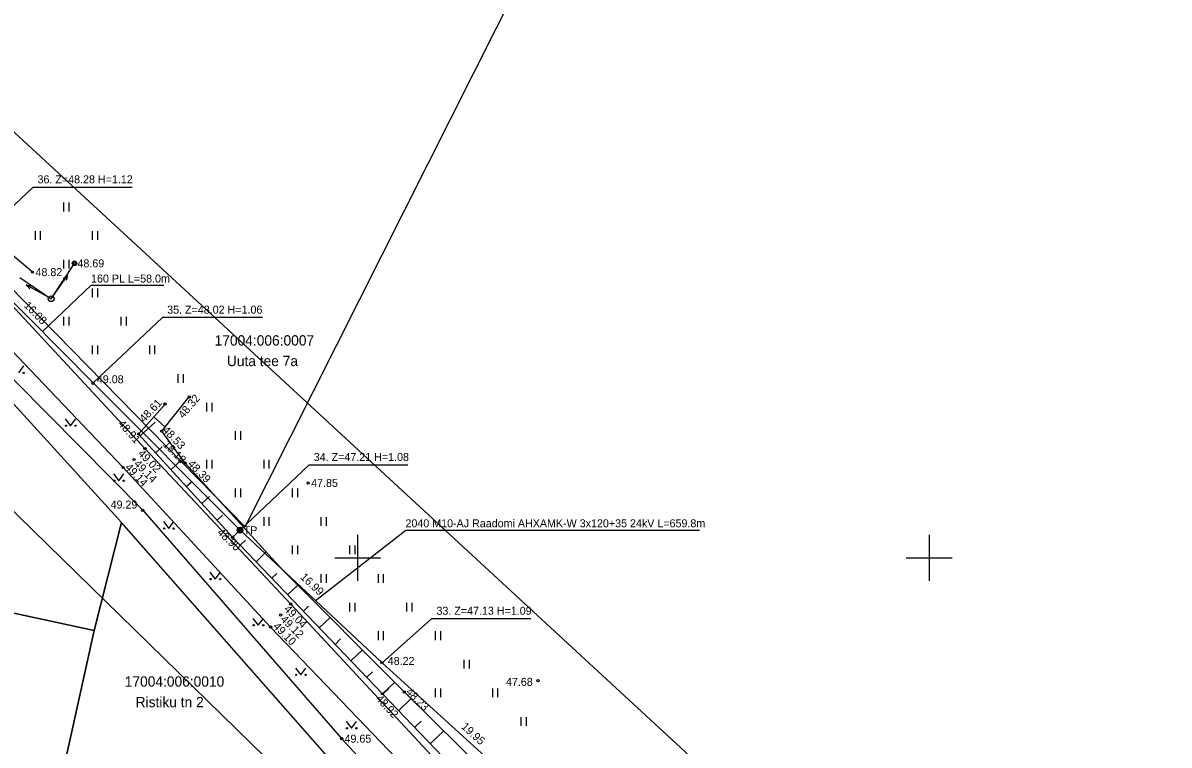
# Model space of a CAD drawing. Extents: x 642747 to 644424, y 6457048 to 6458238.
# Drawn here: x 643970.7 to 644071, y 6457583.6 to 6457646.8 of the extents above; entities that cross this region are included whole.
import ezdxf

# ---------------------------------------------------------------- set-up
doc = ezdxf.new("R2010")
doc.units = 0
for name, color, linetype in [('ABIJOONIS', 7, 'Continuous'), ('AED', 7, 'Continuous'), ('HALJASTUS', 7, 'Continuous'), ('JOONSIDE', 7, 'Continuous'), ('KOORDPUNKT', 7, 'Continuous'), ('KORGUS', 7, 'Continuous'), ('KPKAABEL', 7, 'Continuous'), ('MOOTPIIR', 7, 'Continuous'), ('MPOHULIIN', 7, 'Continuous'), ('PIIR', 7, 'Continuous'), ('POST', 7, 'Continuous'), ('RELJEEF', 7, 'Continuous'), ('TEE', 7, 'Continuous'), ('VORK', 7, 'Continuous')]:
    doc.layers.add(name, color=color, linetype=linetype)

msp = doc.modelspace()

# ---------------------------------------------------------------- linework, layer by layer
at = {"layer": 'ABIJOONIS'}
for points in [[(643972.43, 6457619.79), (643976.71, 6457623.84), (643983.07, 6457623.84)], [(643996.31, 6457596.27), (644004.21, 6457602.42), (644029.91, 6457602.42)]]:
    msp.add_lwpolyline(points, dxfattribs=at)
at = {"layer": 'AED'}
msp.add_line((643971.57, 6457624.99), (643955.99, 6457638.18), dxfattribs=at)
at = {"layer": 'HALJASTUS'}
for p, q in [((643974.29, 6457631.07), (643974.29, 6457630.31)), ((643974.75, 6457631.07), (643974.75, 6457630.31)), ((643971.79, 6457628.57), (643971.79, 6457627.81)), ((643972.25, 6457628.57), (643972.25, 6457627.81)), ((643976.79, 6457628.57), (643976.79, 6457627.81)), ((643977.25, 6457628.57), (643977.25, 6457627.81)), ((643974.29, 6457626.07), (643974.29, 6457625.31)), ((643974.75, 6457626.07), (643974.75, 6457625.31)), ((643976.79, 6457623.57), (643976.79, 6457622.81)), ((643977.25, 6457623.57), (643977.25, 6457622.81)), ((643974.29, 6457621.07), (643974.29, 6457620.31)), ((643974.75, 6457621.07), (643974.75, 6457620.31)), ((643979.29, 6457621.07), (643979.29, 6457620.31)), ((643979.75, 6457621.07), (643979.75, 6457620.31)), ((643976.79, 6457618.57), (643976.79, 6457617.81)), ((643977.25, 6457618.57), (643977.25, 6457617.81)), ((643981.79, 6457618.57), (643981.79, 6457617.81)), ((643982.25, 6457618.57), (643982.25, 6457617.81)), ((643970.37, 6457616.18), (643970.82, 6457616.79)), ((643984.29, 6457616.07), (643984.29, 6457615.31)), ((643984.75, 6457616.07), (643984.75, 6457615.31)), ((643986.79, 6457613.57), (643986.79, 6457612.81)), ((643987.25, 6457613.57), (643987.25, 6457612.81)), ((643974.44, 6457612.17), (643974.9, 6457611.56)), ((643974.9, 6457611.56), (643975.35, 6457612.17)), ((643989.29, 6457611.07), (643989.29, 6457610.31)), ((643989.75, 6457611.07), (643989.75, 6457610.31)), ((643986.79, 6457608.57), (643986.79, 6457607.81)), ((643987.25, 6457608.57), (643987.25, 6457607.81)), ((643991.79, 6457608.57), (643991.79, 6457607.81)), ((643992.25, 6457608.57), (643992.25, 6457607.81)), ((643978.66, 6457607.34), (643979.12, 6457606.74)), ((643979.12, 6457606.74), (643979.57, 6457607.34)), ((643989.29, 6457606.07), (643989.29, 6457605.31)), ((643989.75, 6457606.07), (643989.75, 6457605.31)), ((643994.29, 6457606.07), (643994.29, 6457605.31)), ((643994.75, 6457606.07), (643994.75, 6457605.31)), ((643983.02, 6457603.17), (643983.49, 6457602.56)), ((643983.49, 6457602.56), (643983.93, 6457603.17)), ((643991.79, 6457603.57), (643991.79, 6457602.81)), ((643992.25, 6457603.57), (643992.25, 6457602.81)), ((643996.79, 6457603.57), (643996.79, 6457602.81)), ((643997.25, 6457603.57), (643997.25, 6457602.81)), ((643994.29, 6457601.07), (643994.29, 6457600.31)), ((643994.75, 6457601.07), (643994.75, 6457600.31)), ((643999.29, 6457601.07), (643999.29, 6457600.31)), ((643999.75, 6457601.07), (643999.75, 6457600.31)), ((643987.09, 6457598.74), (643987.55, 6457598.14)), ((643987.55, 6457598.14), (643988, 6457598.74)), ((643996.79, 6457598.57), (643996.79, 6457597.81)), ((643997.25, 6457598.57), (643997.25, 6457597.81)), ((644001.79, 6457598.57), (644001.79, 6457597.81)), ((644002.25, 6457598.57), (644002.25, 6457597.81)), ((643999.29, 6457596.07), (643999.29, 6457595.31)), ((643999.75, 6457596.07), (643999.75, 6457595.31)), ((644004.29, 6457596.07), (644004.29, 6457595.31)), ((644004.75, 6457596.07), (644004.75, 6457595.31)), ((643990.85, 6457594.7), (643991.32, 6457594.1)), ((643991.32, 6457594.1), (643991.76, 6457594.7)), ((644001.79, 6457593.57), (644001.79, 6457592.81)), ((644002.25, 6457593.57), (644002.25, 6457592.81)), ((644006.79, 6457593.57), (644006.79, 6457592.81)), ((644007.25, 6457593.57), (644007.25, 6457592.81)), ((644009.29, 6457591.07), (644009.29, 6457590.31)), ((644009.75, 6457591.07), (644009.75, 6457590.31)), ((643994.57, 6457590.36), (643995.03, 6457589.76)), ((643995.03, 6457589.76), (643995.47, 6457590.36)), ((644006.79, 6457588.57), (644006.79, 6457587.81)), ((644007.25, 6457588.57), (644007.25, 6457587.81)), ((644011.79, 6457588.57), (644011.79, 6457587.81)), ((644012.25, 6457588.57), (644012.25, 6457587.81)), ((644014.29, 6457586.07), (644014.29, 6457585.31)), ((644014.75, 6457586.07), (644014.75, 6457585.31)), ((643999.01, 6457585.69), (643999.48, 6457585.09)), ((643999.48, 6457585.09), (643999.92, 6457585.69))]:
    msp.add_line(p, q, dxfattribs=at)
msp.add_lwpolyline([(643947.9, 6457637.83), (643981.21, 6457604.16), (643998.6, 6457584.18), (644020.54, 6457560.41), (644029.92, 6457549.51)], dxfattribs=at)
for centre in [(643970.8, 6457616.18), (643974.5, 6457611.56), (643975.33, 6457611.56), (643978.72, 6457606.74), (643979.55, 6457606.74), (643983.09, 6457602.56), (643983.91, 6457602.56), (643987.15, 6457598.14), (643987.98, 6457598.14), (643990.92, 6457594.1), (643991.75, 6457594.1), (643994.63, 6457589.76), (643995.46, 6457589.76), (643999.08, 6457585.09), (643999.9, 6457585.09)]:
    msp.add_circle(centre, 0.055, dxfattribs=at)
at = {"layer": 'KOORDPUNKT'}
for p, q in [((643965.56, 6457626.7), (643971.59, 6457632.41)), ((643980.3, 6457632.41), (643971.59, 6457632.41)), ((643976.89, 6457615.31), (643982.93, 6457621.01)), ((643991.68, 6457621.01), (643982.93, 6457621.01)), ((643989.72, 6457602.42), (643995.75, 6457608.12)), ((644004.39, 6457608.12), (643995.75, 6457608.12)), ((644002.15, 6457590.82), (644006.48, 6457594.67)), ((644015.15, 6457594.67), (644006.48, 6457594.67))]:
    msp.add_line(p, q, dxfattribs=at)
for points in [[(643976.89, 6457615.31), (643976.89, 6457615.31), (643976.89, 6457615.31)], [(643989.72, 6457602.42), (643989.72, 6457602.42), (643989.72, 6457602.42)], [(644002.15, 6457590.82), (644002.15, 6457590.82), (644002.15, 6457590.82)]]:
    msp.add_lwpolyline(points, dxfattribs=at)
at = {"layer": 'KORGUS'}
for centre in [(643971.57, 6457624.99), (643975.24, 6457625.76), (643976.85, 6457615.27), (643985.28, 6457614.08), (643983.17, 6457613.45), (643980.84, 6457610.82), (643982.87, 6457611.08), (643981.4, 6457609.56), (643979.5, 6457607.9), (643980.45, 6457608.6), (643984.91, 6457608.29), (643995.68, 6457606.55), (643981.21, 6457604.16), (643989.07, 6457601.8), (643994.16, 6457595.95), (643993.27, 6457594.99), (643992.4, 6457593.94), (644002.15, 6457590.82), (644015.78, 6457589.26), (644002.18, 6457588.1), (644004.09, 6457588.27), (643998.6, 6457584.18)]:
    msp.add_circle(centre, 0.1, dxfattribs=at)
at = {"layer": 'KPKAABEL'}
for points in [[(644103.08, 6457652.71), (644111.13, 6457630.67), (644117.87, 6457612.3), (644117.83, 6457611.89), (644117.53, 6457611.59), (644112.75, 6457607.62), (644102.69, 6457600.12), (644092.7, 6457590.58), (644078.19, 6457577.56), (644066.52, 6457567.37), (644056.9, 6457559.14), (644048.86, 6457552.54), (644048.04, 6457551.93), (644047.16, 6457551.98), (644039.64, 6457557.84), (644029.55, 6457566.38), (644016.9, 6457577.4), (644002.15, 6457590.82), (643989.72, 6457602.42), (643976.89, 6457615.31), (643965.56, 6457626.7)], [(643989.72, 6457602.42), (643976.89, 6457615.31), (643965.56, 6457626.7), (643955.37, 6457636.99), (643948.85, 6457643.5)]]:
    msp.add_lwpolyline(points, dxfattribs=at)
at = {"layer": 'MOOTPIIR'}
msp.add_lwpolyline([(643525.45, 6457467.56), (643537.45, 6457435.46), (643944.85, 6457628.51), (644046.63, 6457529.09), (644067.02, 6457529.09), (644138.41, 6457598.4), (644075.1, 6457775.21), (644046.02, 6457752.58), (644092.47, 6457611.94), (644070.66, 6457576.37), (644041.98, 6457570.72), (643942.22, 6457662.86)], close=True, dxfattribs=at)
at = {"layer": 'MPOHULIIN'}
for p, q in [((643973.35, 6457622.86), (643974.63, 6457624.71)), ((643974.63, 6457624.71), (643974.25, 6457624.42)), ((643974.63, 6457624.71), (643974.5, 6457624.25)), ((643971.02, 6457623.87), (643971.34, 6457623.52)), ((643971.02, 6457623.87), (643971.48, 6457623.78)), ((643972.99, 6457622.78), (643971.02, 6457623.87))]:
    msp.add_line(p, q, dxfattribs=at)
at = {"layer": 'PIIR'}
for points in [[(643958.41, 6457676.3), (643948.83, 6457644.9), (643990.17, 6457602.7), (644016.12, 6457654.27)], [(643950.16, 6457635.14), (643942.8, 6457601.01), (643976.97, 6457593.64), (643979.35, 6457603.09)], [(643976.63, 6457515.36), (643982.89, 6457517.02), (644002.28, 6457577.05), (643979.35, 6457603.09), (643976.97, 6457593.64), (643971.26, 6457567.81), (643957.55, 6457524.74), (643955.72, 6457521.24)], [(643928.3, 6457534.06), (643957.55, 6457524.74), (643971.26, 6457567.81), (643976.97, 6457593.64), (643942.8, 6457601.01)]]:
    msp.add_lwpolyline(points, close=True, dxfattribs=at)
at = {"layer": 'POST'}
msp.add_lwpolyline([(643970.47, 6457624.51), (643973.2, 6457622.66), (643975.24, 6457625.76)], dxfattribs=at)
for centre, radius in [((643975.24, 6457625.76), 0.2), ((643973.2, 6457622.66), 0.25), ((643989.72, 6457602.42), 0.25), ((643989.72, 6457602.42), 0.225), ((643989.72, 6457602.42), 0.2), ((643989.72, 6457602.42), 0.175), ((643989.72, 6457602.42), 0.15), ((643989.72, 6457602.42), 0.125), ((643989.72, 6457602.42), 0.1), ((643989.72, 6457602.42), 0.075), ((643989.72, 6457602.42), 0.05), ((643989.72, 6457602.42), 0.025)]:
    msp.add_circle(centre, radius, dxfattribs=at)
at = {"layer": 'RELJEEF'}
for p, q in [((643982.17, 6457612.32), (643983.16, 6457611.44)), ((643980.98, 6457610.67), (643982.3, 6457611.87)), ((643982.33, 6457609.19), (643982.91, 6457609.72)), ((643983.68, 6457607.71), (643984.67, 6457608.62)), ((643985.02, 6457606.24), (643985.44, 6457606.61)), ((643986.37, 6457604.76), (643987.04, 6457605.37)), ((643987.72, 6457603.28), (643988.2, 6457603.72)), ((643989.07, 6457601.8), (643990.03, 6457602.68)), ((643989.73, 6457601.1), (643990.2, 6457601.55)), ((643991.12, 6457599.66), (643992.01, 6457600.52)), ((643992.5, 6457598.21), (643992.93, 6457598.63)), ((643993.88, 6457596.77), (643994.77, 6457597.62)), ((643995.26, 6457595.32), (643995.72, 6457595.76)), ((643996.65, 6457593.88), (643997.6, 6457594.79)), ((643998.03, 6457592.43), (643998.52, 6457592.9)), ((643999.41, 6457590.99), (644000.42, 6457591.95)), ((644000.79, 6457589.54), (644001.31, 6457590.04)), ((644002.18, 6457588.1), (644003.25, 6457589.12)), ((644002.21, 6457588.06), (644002.75, 6457588.57)), ((644003.59, 6457586.62), (644004.7, 6457587.68)), ((644004.98, 6457585.17), (644005.55, 6457585.72)), ((644006.36, 6457583.73), (644007.54, 6457584.86))]:
    msp.add_line(p, q, dxfattribs=at)
for points in [[(644040.65, 6457556.03), (644032.79, 6457561.53), (644024.27, 6457567.69), (644013.89, 6457578.56), (644004.09, 6457588.27), (643993.47, 6457598.92), (643984.91, 6457608.29), (643982.87, 6457611.08), (643985.28, 6457614.08)], [(644038.52, 6457554.21), (644034.58, 6457556.1), (644028.43, 6457562.43), (644026.5, 6457562.22), (644014.67, 6457575.07), (644002.18, 6457588.1), (643989.07, 6457601.8), (643980.84, 6457610.82), (643983.17, 6457613.45)]]:
    msp.add_lwpolyline(points, dxfattribs=at)
at = {"layer": 'TEE'}
for points in [[(644045.41, 6457537.96), (644044.12, 6457540.28), (644037.14, 6457549.21), (644032.87, 6457554.03), (644030.18, 6457557.18), (644018.06, 6457570.52), (644006.46, 6457582.72), (643994.16, 6457595.95), (643981.4, 6457609.56), (643968.53, 6457623.39), (643956, 6457636.27), (643954.77, 6457637.55)], [(643953.16, 6457635.53), (643954.52, 6457634.2), (643966.75, 6457621.26), (643979.5, 6457607.9), (643992.4, 6457593.94), (644004.79, 6457581.01), (644016.44, 6457568.7), (644028.36, 6457555.55), (644031.31, 6457552.11), (644035.03, 6457547.6), (644042.19, 6457538.29), (644042.99, 6457534.35), (644042.17, 6457531.3), (644041.04, 6457530.63)]]:
    msp.add_lwpolyline(points, dxfattribs=at)
at = {"layer": 'VORK'}
for p, q in [((644000, 6457602), (644000, 6457598)), ((644050, 6457602), (644050, 6457598)), ((643998, 6457600), (644002, 6457600)), ((644048, 6457600), (644052, 6457600))]:
    msp.add_line(p, q, dxfattribs=at)

# ---------------------------------------------------------------- texts
at = {"layer": 'ABIJOONIS'}
for s, p in [('160 PL L=58.0m', (643976.69, 6457624.08)), ('2040 M10-AJ Raadomi AHXAMK-W 3x120+35 24kV L=659.8m', (644004.19, 6457602.67))]:
    msp.add_text(s, height=0.7, dxfattribs=at).set_placement(p)
at = {"layer": 'JOONSIDE'}
for s, rotation, p in [('16.08', 314.8523, (643970.76, 6457622.01)), ('18.18', 314.8523, (643982.93, 6457609.85)), ('16.99', 316.991, (643994.94, 6457598.24)), ('19.95', 317.6998, (644009.02, 6457585.15))]:
    msp.add_text(s, height=0.7, rotation=rotation, dxfattribs=at).set_placement(p)
at = {"layer": 'KOORDPUNKT'}
for s, p in [('36. Z=48.28 H=1.12', (643972.01, 6457632.76)), ('35. Z=48.02 H=1.06', (643983.35, 6457621.36)), ('34. Z=47.21 H=1.08', (643996.17, 6457608.47)), ('33. Z=47.13 H=1.09', (644006.9, 6457595.02))]:
    msp.add_text(s, height=0.7, dxfattribs=at).set_placement(p)
at = {"layer": 'KORGUS'}
for s, p in [(' 48.69', (643975.24, 6457625.41)), (' 48.82', (643971.57, 6457624.64)), ('49.08', (643977.2, 6457615.27)), (' 47.85', (643995.68, 6457606.2)), (' 49.29', (643978.14, 6457604.31)), ('48.22', (644002.64, 6457590.63)), (' 47.68', (644012.72, 6457588.8)), (' 49.65', (643998.6, 6457583.83))]:
    msp.add_text(s, height=0.7, dxfattribs=at).set_placement(p)
for s, rotation, p in [(' 48.32', 50.0132, (643984.6, 6457611.94)), (' 48.61', 46.4488, (643981.16, 6457611.61)), (' 48.91', 311.658, (643978.83, 6457611.88)), (' 48.53', 313.7288, (643982.7, 6457611.31)), (' 49.02', 314.194, (643980.56, 6457609.25)), (' 49.14', 313.6301, (643979.43, 6457608.05)), (' 49.14', 314.6634, (643980.2, 6457608.35)), (' 48.39', 314.2641, (643984.92, 6457608.35)), (' 48.90', 316.3155, (643987.48, 6457602.33)), (' 49.04', 314.4723, (643993.33, 6457595.64)), (' 49.10', 314.1763, (643992.39, 6457594.14)), (' 49.12', 315.1794, (643993.02, 6457594.74)), (' 48.92', 312.4275, (644001.37, 6457587.83)), (' 48.23', 315.2574, (644003.98, 6457588.39))]:
    msp.add_text(s, height=0.7, rotation=rotation, dxfattribs=at).set_placement(p)
at = {"layer": 'PIIR'}
for s, p in [('17004:006:0007', (643987.5, 6457618.57)), ('Uuta tee 7a', (643988.57, 6457616.77)), ('17004:006:0010', (643979.64, 6457588.73)), ('Ristiku tn 2', (643980.59, 6457586.93))]:
    msp.add_text(s, height=0.9, dxfattribs=at).set_placement(p)
at = {"layer": 'POST'}
msp.add_text('TP', height=0.7, dxfattribs=at).set_placement((643990.04, 6457602.06))

doc.saveas('drawing.dxf')
